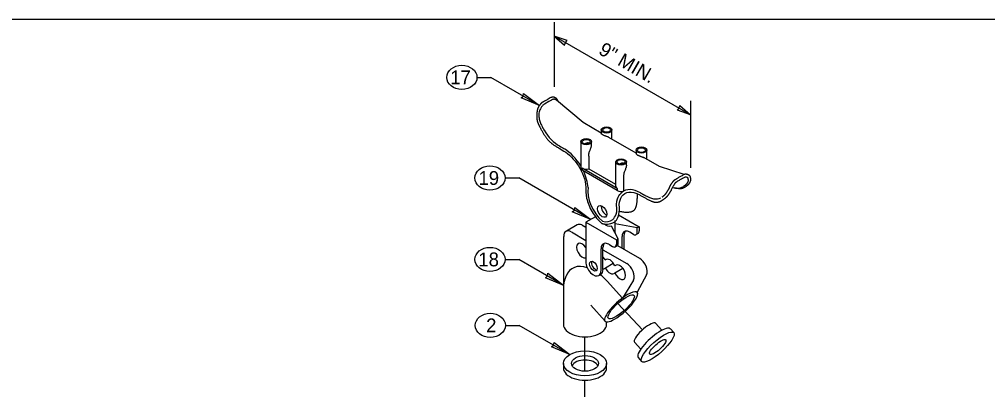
# Model space of a CAD drawing. Extents: x 99862 to 104211, y 98939 to 105076.
# Drawn here: x 101379 to 102500, y 104647 to 105076 of the extents above; entities that cross this region are included whole.
import ezdxf

# ---------------------------------------------------------------- set-up
doc = ezdxf.new("R2010")
doc.units = 0
for name, color, linetype in [('Level 1', 7, 'Continuous'), ('Level 11', 7, 'Continuous'), ('Level 15', 7, 'Continuous'), ('Level 17', 7, 'Continuous'), ('Level 18', 7, 'Continuous'), ('Level 19', 7, 'Continuous'), ('Level 2', 7, 'Continuous'), ('Level 20', 7, 'Continuous'), ('Level 4', 7, 'Continuous'), ('Level 5', 7, 'Continuous')]:
    doc.layers.add(name, color=color, linetype=linetype)

msp = doc.modelspace()

# ---------------------------------------------------------------- linework, layer by layer
at = {"layer": 'Level 1'}
msp.add_lwpolyline([(99862, 102999.5), (103151, 102999.5), (103151, 105075.5), (99862, 105075.5)], close=True, dxfattribs=at)
at = {"layer": 'Level 11'}
for p, q in [((102009, 104677.1), (102009, 104672)), ((102059, 104672), (102059, 104677.1))]:
    msp.add_line(p, q, dxfattribs=at)
msp.add_ellipse((102034, 104677.1), major_axis=(15.6, 0), ratio=0.57735, dxfattribs=at)
for major_axis, start_param, end_param in [((-15.6, 0), 3.428349, 5.996429), ((-25, 0), 6.283185, 9.424778)]:
    msp.add_ellipse((102034, 104672), major_axis=major_axis, ratio=0.57735, start_param=start_param, end_param=end_param, dxfattribs=at)
at = {"layer": 'Level 15'}
for p, q in [((101998.3, 105072.2), (101998.3, 104997.3)), ((102156.1, 104965.1), (101998.3, 105056.2)), ((101908.9, 105008.3), (101924.9, 105008.3)), ((101981.2, 104975.8), (101924.9, 105008.3)), ((102156.1, 104981.1), (102156.1, 104903.7)), ((101941.4, 104891.8), (101957.4, 104891.8)), ((102040.6, 104843.7), (101957.4, 104891.8)), ((101941.4, 104797.5), (101957.4, 104797.5)), ((102009.3, 104767.5), (101957.4, 104797.5)), ((102100.5, 104715.9), (102072.2, 104746.6)), ((101941.8, 104721.1), (101957.8, 104721.1)), ((102016.4, 104687.3), (101957.8, 104721.1)), ((102034, 104668), (102034, 104707.9)), ((102034, 104618.4), (102034, 104657.5))]:
    msp.add_line(p, q, dxfattribs=at)
for points in [[(101998.3, 105056.2), (102010.3, 105045.7), (102011.3, 105048.7), (102013.4, 105051)], [(101981.2, 104975.8), (101959.9, 104984.7), (101962.3, 104986.7), (101962.9, 104989.8)], [(102156.1, 104965.1), (102141, 104970.3), (102143.1, 104972.6), (102144, 104975.6)], [(102040.6, 104843.7), (102019.3, 104852.6), (102021.7, 104854.6), (102022.3, 104857.7)], [(102009.3, 104767.5), (101988.1, 104776.3), (101990.5, 104778.4), (101991.1, 104781.5)], [(102016.4, 104687.3), (101995.1, 104696.1), (101997.5, 104698.2), (101998.1, 104701.3)]]:
    msp.add_lwpolyline(points, close=True, dxfattribs=at)
at = {"layer": 'Level 17'}
for p, q in [((102032, 104955.9), (102001, 104981.8)), ((102052.7, 104943.9), (102032, 104955.9)), ((102052.7, 104947.4), (102052.7, 104943.5)), ((102093.1, 104920.6), (102061.6, 104938.8)), ((102065.2, 104936.7), (102065.2, 104947.4)), ((102004, 104926.4), (102009.5, 104923)), ((102029.1, 104933.8), (102029.1, 104903.1)), ((102041.6, 104929.9), (102041.6, 104933.8)), ((102038.3, 104917.1), (102038.3, 104902.5)), ((102093.1, 104924.1), (102093.1, 104920.2)), ((102120.2, 104905), (102102.1, 104915.5)), ((102105.6, 104913.4), (102105.6, 104924.1)), ((102069.5, 104910.4), (102069.5, 104882.4)), ((102082, 104906.6), (102082, 104910.4)), ((102149, 104895.8), (102120.2, 104905)), ((102030.6, 104903.4), (102030.6, 104900.8)), ((102030.6, 104903.4), (102030.6, 104900.8)), ((102030.6, 104903.4), (102030.6, 104903.4)), ((102030.9, 104903.1), (102030.6, 104903.4)), ((102071.4, 104877.3), (102030.6, 104900.8)), ((102071.4, 104879.8), (102030.9, 104903.1)), ((102038.3, 104902.5), (102069.5, 104884.5)), ((102078.7, 104893.8), (102078.7, 104876.6)), ((102071.4, 104879.8), (102071.4, 104877.3)), ((102097.6, 104872.1), (102103.1, 104869.2))]:
    msp.add_line(p, q, dxfattribs=at)
for centre, major_axis in [((102059, 104947.4), (-6.25, 0)), ((102059, 104947.4), (-4.69, 0)), ((102035.4, 104933.8), (-6.25, 0)), ((102035.4, 104933.8), (4.69, 0)), ((102099.4, 104924.1), (6.25, 0)), ((102099.4, 104924.1), (4.69, 0)), ((102075.8, 104910.4), (6.25, 0)), ((102075.8, 104910.4), (-4.69, 0)), ((102053.9, 104853.1), (3.75, -6.5))]:
    msp.add_ellipse(centre, major_axis=major_axis, ratio=0.57735, dxfattribs=at)
for centre, major_axis, ratio, start_param, end_param in [((102003.9, 104958.8), (-17.7, 31.3), 0.57735, 1.6138, 2.395219), ((102010.1, 104893.6), (-19.5, 33.8), 0.57735, 4.736377, 5.49473), ((102035.4, 104903.1), (-6.25, 0), 0.57735, 6.283185, 6.98269), ((102035.4, 104905.7), (-6.25, 0), 0.57735, 0.699505, 0.785398), ((102035.4, 104905.7), (-6.25, 0), 0.57735, 0.785398, 2.061945), ((102010.1, 104893.6), (-19.5, 33.8), 0.57735, 4.022982, 4.565814), ((102075.8, 104882.4), (-6.25, 0), 0.57735, 6.283185, 7.068583), ((102128.9, 104914.3), (-18.7, 32.5), 0.577329, 2.604955, 3.160056), ((102059.7, 104863.7), (-15.9, 27.5), 0.57735, 0.616549, 2.107388), ((102075.8, 104879.8), (6.25, 0), 0.57735, 3.926991, 5.203538), ((102098.2, 104842.7), (-19.5, 33.8), 0.57735, 5.500844, 6.398051), ((102104.7, 104900.4), (-18, 31.1), 0.57735, 2.31717, 3.098589), ((102058.2, 104855.6), (3.75, -6.5), 0.57735, 3.754385, 5.670393), ((102048.6, 104870.1), (15.9, -27.5), 0.57735, 5.746594, 6.3945), ((102048.6, 104870.1), (15.9, -27.5), 0.57735, 0.13318472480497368, 0.13318473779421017)]:
    msp.add_ellipse(centre, major_axis=major_axis, ratio=ratio, start_param=start_param, end_param=end_param, dxfattribs=at)
for points, degree in [([(101998.3, 104985.3), (101996.8, 104985.7), (101995.1, 104985.4), (101985.1, 104979.6)], 2), ([(101998.8, 104982.9), (101998.3, 104983), (101997.7, 104983), (101996.6, 104982.8), (101996, 104982.6), (101987, 104977.4)], 3), ([(102003, 104980.5), (102002, 104982.7), (102000.4, 104984.4), (101998.3, 104985.3)], 2), ([(102001, 104981.8), (102000.3, 104982.3), (101999.6, 104982.7), (101998.8, 104982.9)], 2), ([(101981.1, 104975.7), (101979.5, 104973.1), (101978.6, 104970.2), (101978.3, 104967.3)], 2), ([(101983.7, 104974.2), (101982.9, 104973.1), (101982.3, 104971.9), (101981.4, 104969.4), (101981, 104968.1), (101980.7, 104966.9)], 3), ([(101985.1, 104979.6), (101983.7, 104978.8), (101982.3, 104977.4), (101981.1, 104975.7)], 2), ([(101987, 104977.4), (101986.4, 104977), (101985.8, 104976.6), (101984.7, 104975.5), (101984.2, 104974.9), (101983.7, 104974.2)], 3), ([(101978.3, 104967.3), (101977.9, 104961.4), (101979.2, 104955.5), (101982, 104950.3)], 2), ([(101980.7, 104966.9), (101980.4, 104964.2), (101980.7, 104961.5), (101982, 104956.2), (101983, 104953.7), (101984.3, 104951.3)], 3), ([(101982, 104950.2), (101987.4, 104939.9), (101995.6, 104930.9), (102004, 104926.4)], 2), ([(101984.3, 104951.3), (101984.6, 104950.8), (101984.8, 104950.3), (101985.1, 104949.8)], 2), ([(101985.1, 104949.8), (101985.6, 104948.9), (101986, 104948), (101986.6, 104947.2)], 2), ([(102061.7, 104938.8), (102061.4, 104938.9), (102061.2, 104939.1), (102060.3, 104939.5), (102059.6, 104939.7), (102058.1, 104940.3), (102057.3, 104940.5), (102055.8, 104941.1), (102055.1, 104941.4), (102054, 104942.1), (102053.5, 104942.4), (102052.9, 104943), (102052.7, 104943.3), (102052.7, 104943.5), (102052.7, 104943.5), (102052.7, 104943.5)], 3), ([(102004.6, 104928.9), (102005.8, 104928.2), (102006.9, 104927.5), (102008, 104926.8), (102008.7, 104926.4), (102009.4, 104925.9), (102010.1, 104925.5)], 3), ([(102038.8, 104931.9), (102038.7, 104931.9), (102038.7, 104931.9), (102038.2, 104932.2), (102037.6, 104932.4), (102036.3, 104932.3), (102035.6, 104932.2), (102034.7, 104931.7), (102034.4, 104931.4), (102034.1, 104931.2)], 3), ([(102038.3, 104917.1), (102038.2, 104918.5), (102038.4, 104919.9), (102039, 104922), (102039.3, 104922.7), (102039.9, 104924.1), (102040.2, 104924.9), (102040.8, 104926.4), (102041.1, 104927.1), (102041.5, 104928.6), (102041.6, 104929.3), (102041.6, 104929.9)], 3), ([(102009.5, 104923), (102015.2, 104919.7), (102027.8, 104907.3), (102034.4, 104889.6), (102035.1, 104881.3)], 3), ([(102093.1, 104920.2), (102093.1, 104920.2), (102093.1, 104920.2), (102093.2, 104920), (102093.3, 104919.7), (102093.9, 104919.1), (102094.4, 104918.7), (102095.5, 104918.1), (102096.2, 104917.8), (102097.7, 104917.2), (102098.5, 104916.9), (102100, 104916.4), (102100.7, 104916.1), (102101.6, 104915.7), (102101.8, 104915.6), (102102.1, 104915.4)], 3), ([(102079.2, 104908.6), (102079.1, 104908.6), (102079.1, 104908.6), (102078.6, 104908.9), (102078, 104909), (102076.7, 104909), (102076.1, 104908.8), (102075.1, 104908.3), (102074.8, 104908.1), (102074.5, 104907.8)], 3), ([(102082, 104906.5), (102082, 104905.9), (102081.9, 104905.2), (102081.5, 104903.8), (102081.2, 104903.1), (102080.3, 104900.8), (102079.7, 104899.4), (102079, 104897.3), (102078.9, 104896.6), (102078.7, 104895.2), (102078.7, 104894.5), (102078.7, 104893.8)], 3), ([(102139.3, 104890.6), (102149.3, 104896.4), (102150.9, 104896.7), (102152.6, 104896.2)], 2), ([(102140.8, 104887.9), (102149.8, 104893.1), (102151, 104893.4), (102151.5, 104893.3)], 2), ([(102152, 104893), (102152.7, 104892.4), (102153.1, 104891.7), (102153.2, 104890.7)], 2), ([(102152.6, 104896.2), (102154.5, 104895.4), (102155.8, 104893.7), (102156.1, 104891.7)], 2), ([(102131.4, 104879.6), (102132.4, 104881.9), (102133.7, 104884.4), (102135.3, 104886.8)], 2), ([(102134.3, 104878.3), (102134.7, 104879.3), (102135.7, 104881.5), (102137.1, 104883.9), (102137.9, 104885)], 3), ([(102135.4, 104886.8), (102136.5, 104888.4), (102137.9, 104889.8), (102139.3, 104890.6)], 2), ([(102152, 104882.8), (102148.2, 104879.8), (102143.1, 104879), (102137.6, 104880.4)], 2), ([(102137.9, 104885), (102138.8, 104886.3), (102139.8, 104887.3), (102140.9, 104887.9)], 2), ([(102150, 104883.3), (102149.3, 104882.8), (102148.7, 104882.4), (102148, 104882)], 2), ([(102152.3, 104885.9), (102151.7, 104885), (102150.9, 104884.1), (102150, 104883.3)], 2), ([(102155.5, 104887), (102154.7, 104885.5), (102153.6, 104884.1), (102152, 104882.8)], 2), ([(102153.2, 104890.7), (102153.5, 104889), (102153.2, 104887.4), (102152.3, 104885.9)], 2), ([(102156.1, 104891.7), (102156.3, 104890.3), (102156.1, 104888.7), (102155.6, 104887.3), (102155.5, 104887)], 3), ([(102035.1, 104881.4), (102034.6, 104878.1), (102034.9, 104868.7), (102041.2, 104852.5), (102049.4, 104842.7), (102053.4, 104839.3)], 3), ([(102070.4, 104861.2), (102070.9, 104866.8), (102073, 104871.8), (102076.4, 104874.9), (102076.6, 104875)], 3), ([(102073.5, 104861), (102073.9, 104864.7), (102076.1, 104871.4), (102083.9, 104876.8), (102092.5, 104875), (102097.5, 104872.2)], 3), ([(102073.6, 104853.3), (102088.4, 104850.4), (102095.1, 104860.7), (102094.6, 104873.6)], 2), ([(102098.1, 104874.7), (102099.9, 104873.7), (102101.8, 104872.7), (102103.6, 104871.7)], 2), ([(102123.5, 104869.9), (102126.4, 104872.1), (102129, 104875.4), (102131.4, 104879.6)], 2), ([(102126.2, 104867.9), (102128.9, 104870.1), (102131.6, 104873.6), (102134.3, 104878.3)], 2), ([(102057.2, 104838.4), (102057.7, 104838.4), (102061.2, 104838.1), (102071.2, 104840.7), (102074.6, 104852), (102073.5, 104861)], 3), ([(102066.1, 104843.8), (102066.2, 104843.9), (102069.8, 104847.2), (102071.4, 104853.6), (102070.4, 104861)], 3), ([(102103, 104869.2), (102111.5, 104864), (102120.4, 104863.3), (102126.1, 104867.9)], 2), ([(102053.6, 104839.2), (102054.8, 104838.8), (102056, 104838.6), (102057.2, 104838.4)], 2)]:
    msp.add_open_spline(points, degree=degree, dxfattribs=at)
at = {"layer": 'Level 18'}
for p, q in [((102025.1, 104837.5), (102012.5, 104830.2)), ((102030.4, 104837.4), (102034.9, 104834.7)), ((102018.2, 104829.3), (102034.9, 104819.6)), ((102009.3, 104767.5), (102009.3, 104824.2)), ((102054.8, 104808.6), (102082.3, 104792.7)), ((102071.5, 104813.6), (102097.3, 104798.8)), ((102077.3, 104752.6), (102059.8, 104772.2)), ((102090.3, 104773.6), (102077.3, 104752.6)), ((102105.3, 104779.6), (102094.6, 104759.4)), ((102009, 104762.2), (102009, 104722.3)), ((102040.6, 104744.6), (102057.3, 104725.9)), ((102059, 104722.3), (102059, 104725.1)), ((102115.8, 104723.5), (102123.1, 104715.4)), ((102136.9, 104712.7), (102132.9, 104717.2)), ((102091.5, 104701.6), (102098.6, 104693.6)), ((102095.6, 104683.9), (102099.6, 104679.4))]:
    msp.add_line(p, q, dxfattribs=at)
for centre, major_axis, ratio, start_param, end_param in [((102031.4, 104826.7), (-6.3, 10.8), 0.57735, 5.614919, 6.283185), ((102018.2, 104819.1), (-6.3, 10.8), 0.57735, 5.497787, 7.068583), ((102030.8, 104807.8), (-4.69, 8.12), 0.57735, 4.823124, 9.314051), ((102042.9, 104746.9), (-23.3, 40.4), 0.57735, 5.689816, 6.702979), ((102051.7, 104795.7), (-4.69, 8.12), 0.57735, 4.483455, 5.013808), ((102063, 104789.2), (-4.69, 8.12), 0.57735, 4.483455, 6.512119), ((102074.3, 104782.7), (-4.69, 8.12), 0.57735, 1.341862, 6.512119), ((102082.3, 104782.5), (6.2, -10.8), 0.57735, 0.347397, 2.356194), ((102097.3, 104788.6), (6.2, -10.8), 0.57735, 0.347397, 2.356194), ((102052, 104795.1), (-4.69, 8.12), 0.57735, 2.801217, 3.370527), ((102063, 104789.2), (-4.69, 8.12), 0.57735, 1.404224, 3.370527), ((102045.8, 104745.8), (-23.3, 40.4), 0.57735, 5.059786, 5.31784), ((102075.9, 104742.6), (-18.6, -16.7), 0.277977, 1.054941, 4.067589), ((102075.9, 104742.6), (-18.6, -16.7), 0.277977, 4.067589, 7.338126), ((102103.6, 104712.6), (12.2, 10.9), 0.277977, 0.174514, 3.16344), ((102034, 104722.3), (-25, 0), 0.57735, 6.283185, 9.424778), ((102114.2, 104700.5), (18.6, 16.7), 0.277977, 6.283185, 9.424778), ((102103.6, 104712.6), (12.2, 10.9), 0.277977, 6.283183, 6.457699)]:
    msp.add_ellipse(centre, major_axis=major_axis, ratio=ratio, start_param=start_param, end_param=end_param, dxfattribs=at)
for major_axis in [(18.6, 16.7), (9.28, 8.3)]:
    msp.add_ellipse((102118.2, 104696), major_axis=major_axis, ratio=0.277977, dxfattribs=at)
msp.add_open_spline([(102012.1, 104778.3), (102010, 104773.2), (102009, 104767.7), (102009, 104762.2)], degree=2, dxfattribs=at)
at = {"layer": 'Level 19'}
for p, q in [((102072.8, 104849.3), (102096.8, 104835.4)), ((102046.2, 104847), (102034.9, 104840.5)), ((102046.2, 104847), (102034.9, 104840.5)), ((102034.9, 104840.5), (102034.9, 104794.8)), ((102034.9, 104840.5), (102034.9, 104794.8)), ((102034.9, 104840.5), (102070.3, 104820.1)), ((102094.6, 104834.1), (102069.1, 104838.6)), ((102072.5, 104821.4), (102064.7, 104836.2)), ((102090.2, 104826.5), (102085.8, 104829)), ((102095.5, 104827.4), (102093.3, 104826.2)), ((102096.8, 104835.4), (102094.6, 104834.1)), ((102094.6, 104831.6), (102094.6, 104834.1)), ((102094.6, 104829.2), (102094.6, 104831.6)), ((102096.8, 104835.4), (102096.8, 104830.5)), ((102061.5, 104815), (102065.9, 104812.4)), ((102061.5, 104815), (102065.9, 104812.4)), ((102070.3, 104820.1), (102072.5, 104821.4)), ((102070.3, 104820.1), (102070.3, 104815.2)), ((102072.5, 104818.8), (102072.5, 104821.4)), ((102072.5, 104816.4), (102072.5, 104818.8)), ((102076.9, 104817.6), (102076.9, 104823.9)), ((102076.9, 104810.5), (102076.9, 104817.6)), ((102079.1, 104825.2), (102079.1, 104818.8)), ((102079.1, 104818.8), (102079.1, 104809.2)), ((102052.6, 104803.5), (102052.6, 104809.9)), ((102052.6, 104784.7), (102052.6, 104803.5)), ((102054.8, 104804.8), (102054.8, 104811.2)), ((102054.8, 104804.8), (102054.8, 104811.2)), ((102054.8, 104786), (102054.8, 104804.8)), ((102054.8, 104786), (102054.8, 104804.8)), ((102069, 104812.1), (102071.2, 104813.4)), ((102050, 104778.9), (102052.2, 104780.2)), ((102050, 104778.9), (102052.2, 104780.2))]:
    msp.add_line(p, q, dxfattribs=at)
for centre, major_axis, start_param, end_param in [((102062.9, 104839.7), (6.25, 0), 3.488598, 5.007384), ((102085.8, 104818.8), (6.3, -10.8), 2.965861, 3.926991), ((102088, 104820.1), (6.3, -10.8), 3.319303, 3.926991), ((102085.8, 104818.8), (6.3, -10.8), 2.356194, 2.965861), ((102090.2, 104831.6), (3.13, -5.41), 5.497787, 6.323034), ((102090.2, 104831.6), (3.13, -5.41), 0.039849, 0.820027), ((102092.4, 104832.8), (3.13, -5.41), 0, 0.820027), ((102061.5, 104804.8), (6.3, -10.8), 2.97025, 3.926991), ((102063.7, 104806.1), (6.3, -10.8), 3.319303, 3.926991), ((102063.7, 104806.1), (6.3, -10.8), 3.319303, 3.926991), ((102061.5, 104804.8), (6.3, -10.8), 2.356194, 2.97025), ((102061.5, 104804.8), (6.3, -10.8), 2.356194, 2.97025), ((102065.9, 104817.5), (3.13, -5.41), 0.085827, 0.820027), ((102068.1, 104818.8), (3.13, -5.41), 0, 0.820027), ((102065.9, 104817.5), (3.13, -5.41), 5.497787, 6.369012), ((102043.8, 104789.7), (6.3, -10.8), 3.927, 6.298242), ((102043.8, 104789.7), (6.3, -10.8), 3.927, 6.298242), ((102046, 104791), (3.13, -5.41), 3.50296, 5.921818), ((102043.8, 104789.7), (6.3, -10.8), 0.015056, 0.795013), ((102046, 104791), (6.3, -10.8), 0, 0.795013), ((102046, 104791), (6.3, -10.8), 0, 0.795013)]:
    msp.add_ellipse(centre, major_axis=major_axis, ratio=0.57735, start_param=start_param, end_param=end_param, dxfattribs=at)
msp.add_ellipse((102043.8, 104789.7), major_axis=(3.13, -5.41), ratio=0.57735, dxfattribs=at)
at = {"layer": 'Level 2'}
msp.add_ellipse((102034, 104677.1), major_axis=(25, 0), ratio=0.57735, dxfattribs=at)
at = {"layer": 'Level 20'}
for centre in [(101891.4, 105008.3), (101923.9, 104891.8), (101923.9, 104797.5), (101924.3, 104721.1)]:
    msp.add_ellipse(centre, major_axis=(-17.5, 0), ratio=0.8, dxfattribs=at)
at = {"layer": 'Level 4'}
msp.add_line((102069.1, 104829.5), (102069.1, 104842.5), dxfattribs=at)
msp.add_ellipse((102062.9, 104829.5), major_axis=(6.25, 0), ratio=0.57735, start_param=5.972868, end_param=6.283185, dxfattribs=at)
at = {"layer": 'Level 5'}
for p, q in [((102057.6, 104787.9), (102066.8, 104793.2)), ((102068.6, 104781.9), (102077.8, 104787.2))]:
    msp.add_line(p, q, dxfattribs=at)
msp.add_ellipse((102075.9, 104742.6), major_axis=(-14.9, -13.3), ratio=0.277977, dxfattribs=at)

# ---------------------------------------------------------------- texts
at = {"layer": 'Level 20'}
for s, rotation, p in [('9" MIN.', 330.0064, (102048.5, 105036.1)), ('2', 360, (101919.5, 104713.1))]:
    msp.add_text(s, height=16, rotation=rotation, dxfattribs=at).set_placement(p)
for s, p in [('17', (101877.9, 105000.3)), ('19', (101910.7, 104883.8)), ('18', (101910.5, 104789.5))]:
    msp.add_text(s, height=16, dxfattribs=at).set_placement(p)

doc.saveas('drawing.dxf')
